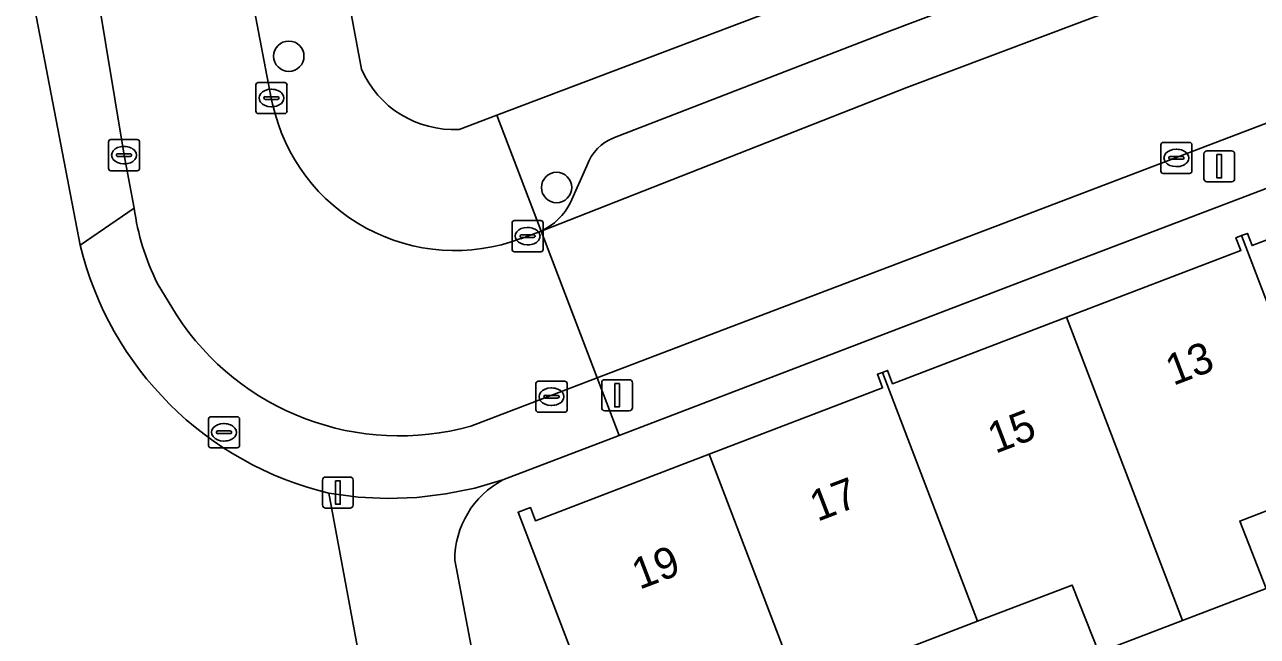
# Model space of a CAD drawing. Extents: x 159262 to 160143, y 383399 to 384319.
# Drawn here: x 159355.19 to 159394.93, y 383819.43 to 383839.14 of the extents above; entities that cross this region are included whole.
import ezdxf

# ---------------------------------------------------------------- set-up
doc = ezdxf.new("R2010")
doc.units = 0
for name, color, linetype in [('IMGEO_Boom', 7, 'Continuous'), ('IMGEO_Erf', 7, 'Continuous'), ('IMGEO_Groenvoorziening', 7, 'Continuous'), ('IMGEO_Kolk', 7, 'Continuous'), ('IMGEO_Lichtmast', 7, 'Continuous'), ('IMGEO_Pand', 7, 'Continuous'), ('IMGEO_Pand_nummerreeks', 7, 'Continuous'), ('IMGEO_Parkeervlak_open', 7, 'Continuous'), ('IMGEO_Rijbaan_lokaal_open', 7, 'Continuous'), ('IMGEO_Rioolput', 7, 'Continuous'), ('IMGEO_Voetpad_open', 7, 'Continuous')]:
    doc.layers.add(name, color=color, linetype=linetype)

msp = doc.modelspace()

# ---------------------------------------------------------------- linework, layer by layer
at = {"layer": 'IMGEO_Boom'}
for centre in [(159363.708, 383838.12), (159372.339, 383833.89)]:
    msp.add_circle(centre, 0.489, dxfattribs=at)
at = {"layer": 'IMGEO_Erf'}
for points in [[(159397.789, 383869.946), (159393.849, 383868.425), (159390.056, 383866.962), (159389.5, 383868.402), (159385.489, 383866.763), (159386.378, 383864.405), (159384.999, 383863.885), (159382.63, 383862.992), (159378.689, 383861.507), (159377.8, 383863.866), (159375.594, 383863.034), (159376.483, 383860.676), (159372.524, 383859.184), (159371.635, 383861.542), (159368.487, 383860.413), (159369.569, 383857.597), (159370.651, 383854.78), (159371.732, 383851.964), (159372.814, 383849.148), (159373.896, 383846.331), (159374.978, 383843.515), (159369.061, 383841.246), (159365.629, 383839.957), (159366.048, 383837.703)], [(159369.194, 383835.764), (159370.416, 383836.226), (159382.457, 383840.783), (159431.75, 383859.554)], [(159434.697, 383848.89), (159387.616, 383830.972), (159374.358, 383825.902), (159370.61, 383824.469)], [(159374.298, 383815.054), (159371.098, 383823.424), (159371.496, 383823.577), (159371.658, 383823.154), (159377.252, 383825.293), (159382.847, 383827.432), (159382.679, 383827.873), (159382.84, 383827.934), (159383.002, 383827.996), (159383.166, 383827.567), (159388.779, 383829.713), (159394.394, 383831.86), (159394.237, 383832.27), (159394.42, 383832.34), (159394.607, 383832.411), (159394.756, 383832.021), (159400.338, 383834.155)], [(159397.482, 383824.337), (159394.356, 383823.141), (159395.215, 383820.973), (159392.518, 383819.942), (159389.818, 383818.909), (159388.959, 383821.077), (159385.91, 383819.911), (159380.153, 383817.708)], [(159369.056, 383821.878), (159372.012, 383806.327), (159372.571, 383803.406), (159376.551, 383804.927), (159375.402, 383807.935), (159382.941, 383810.816), (159384.09, 383807.808), (159397.412, 383813.025), (159396.531, 383815.33), (159400.367, 383816.796), (159406.149, 383819.006), (159407.03, 383816.7), (159408.972, 383817.511), (159408.457, 383818.833), (159412.284, 383820.326), (159416.246, 383821.872), (159415.776, 383823.077)]]:
    msp.add_lwpolyline(points, dxfattribs=at)
for centre, radius, start, end in [((159369.017, 383838.998), 3.239, 203.5692, 273.1366), ((159371.982, 383821.884), 2.926, 117.9652, 180.1268)]:
    msp.add_arc(centre, radius, start, end, dxfattribs=at)
at = {"layer": 'IMGEO_Groenvoorziening'}
for points in [[(159354.9, 383842.891), (159350.307, 383841.994), (159347.636, 383855.565), (159344.735, 383870.683), (159342.623, 383870.295), (159354.405, 383809.755), (159367.99, 383812.463), (159367.685, 383814.072), (159369.306, 383814.377), (159368.687, 383817.552), (159366.931, 383817.307), (159366.196, 383817.565), (159364.998, 383824.037)], [(159356.981, 383832.035), (159354.9, 383842.891)]]:
    msp.add_lwpolyline(points, dxfattribs=at)
msp.add_arc((159367.542, 383834.604), 10.869, 193.672, 256.4639, dxfattribs=at)
at = {"layer": 'IMGEO_Kolk'}
for p, q in [((159362.648, 383836.348), (159362.648, 383837.2)), ((159362.723, 383837.274), (159363.575, 383837.274)), ((159363.136, 383837.054), (159363.161, 383837.054)), ((159363.649, 383837.2), (159363.649, 383836.348)), ((159362.907, 383836.768), (159362.907, 383836.78)), ((159363.345, 383836.731), (159362.947, 383836.731)), ((159362.95, 383836.817), (159363.348, 383836.817)), ((159363.391, 383836.78), (159363.391, 383836.768)), ((159363.575, 383836.274), (159362.723, 383836.274)), ((159363.159, 383836.494), (159363.134, 383836.494)), ((159357.971, 383835.432), (159358.823, 383835.432)), ((159357.896, 383834.506), (159357.896, 383835.358)), ((159358.384, 383835.212), (159358.409, 383835.212)), ((159358.897, 383835.358), (159358.897, 383834.506)), ((159391.816, 383834.416), (159391.816, 383835.268)), ((159391.891, 383835.342), (159392.743, 383835.342)), ((159392.304, 383835.122), (159392.329, 383835.122)), ((159392.817, 383835.268), (159392.817, 383834.416)), ((159358.155, 383834.926), (159358.155, 383834.938)), ((159358.593, 383834.889), (159358.195, 383834.889)), ((159358.198, 383834.975), (159358.596, 383834.975)), ((159358.407, 383834.652), (159358.382, 383834.652)), ((159358.639, 383834.938), (159358.639, 383834.926)), ((159392.075, 383834.836), (159392.075, 383834.848)), ((159392.513, 383834.799), (159392.115, 383834.799)), ((159392.118, 383834.885), (159392.516, 383834.885)), ((159392.559, 383834.848), (159392.559, 383834.836)), ((159358.823, 383834.432), (159357.971, 383834.432)), ((159392.743, 383834.342), (159391.891, 383834.342)), ((159392.327, 383834.562), (159392.302, 383834.562)), ((159370.902, 383831.896), (159370.902, 383832.748)), ((159370.977, 383832.822), (159371.829, 383832.822)), ((159371.903, 383832.748), (159371.903, 383831.896)), ((159371.161, 383832.316), (159371.161, 383832.328)), ((159371.599, 383832.279), (159371.201, 383832.279)), ((159371.204, 383832.365), (159371.602, 383832.365)), ((159371.39, 383832.602), (159371.415, 383832.602)), ((159371.645, 383832.328), (159371.645, 383832.316)), ((159371.829, 383831.822), (159370.977, 383831.822)), ((159371.413, 383832.042), (159371.388, 383832.042)), ((159371.674, 383826.724), (159371.674, 383827.576)), ((159371.749, 383827.65), (159372.601, 383827.65)), ((159372.675, 383827.576), (159372.675, 383826.724)), ((159371.933, 383827.144), (159371.933, 383827.156)), ((159372.371, 383827.107), (159371.973, 383827.107)), ((159371.976, 383827.193), (159372.374, 383827.193)), ((159372.162, 383827.43), (159372.187, 383827.43)), ((159372.417, 383827.156), (159372.417, 383827.144)), ((159372.601, 383826.65), (159371.749, 383826.65)), ((159372.185, 383826.87), (159372.16, 383826.87))]:
    msp.add_line(p, q, dxfattribs=at)
for points in [[(159362.648, 383836.348), (159362.648, 383837.2)], [(159362.723, 383837.274), (159363.575, 383837.274)], [(159363.649, 383837.2), (159363.649, 383836.348)], [(159363.575, 383836.274), (159362.723, 383836.274)], [(159357.971, 383835.432), (159358.823, 383835.432)], [(159357.896, 383834.506), (159357.896, 383835.358)], [(159358.897, 383835.358), (159358.897, 383834.506)], [(159391.816, 383834.416), (159391.816, 383835.268)], [(159391.891, 383835.342), (159392.743, 383835.342)], [(159392.817, 383835.268), (159392.817, 383834.416)], [(159358.823, 383834.432), (159357.971, 383834.432)], [(159392.743, 383834.342), (159391.891, 383834.342)], [(159370.902, 383831.896), (159370.902, 383832.748)], [(159370.977, 383832.822), (159371.829, 383832.822)], [(159371.903, 383832.748), (159371.903, 383831.896)], [(159371.829, 383831.822), (159370.977, 383831.822)], [(159371.674, 383826.724), (159371.674, 383827.576)], [(159371.749, 383827.65), (159372.601, 383827.65)], [(159372.675, 383827.576), (159372.675, 383826.724)], [(159372.601, 383826.65), (159371.749, 383826.65)]]:
    msp.add_lwpolyline(points, dxfattribs=at)
for centre, radius, start, end in [((159362.725, 383837.198), 0.0765, 91.552, 178.448), ((159362.725, 383837.198), 0.0765, 91.552, 178.448), ((159363.573, 383837.198), 0.0765, 1.552, 88.448), ((159363.573, 383837.198), 0.0765, 1.552, 88.448), ((159362.947, 383836.777), 0.0403, 85.8775, 175.7526), ((159362.944, 383836.767), 0.0366, 178.938, 274.7102), ((159363.348, 383836.774), 0.043, 264.8664, 352.4533), ((159363.352, 383836.779), 0.0386, 1.7309, 96.639), ((159362.725, 383836.35), 0.0765, 181.552, 268.448), ((159362.725, 383836.35), 0.0765, 181.552, 268.448), ((159363.573, 383836.35), 0.0765, 271.552, 358.448), ((159363.573, 383836.35), 0.0765, 271.552, 358.448), ((159357.973, 383835.356), 0.0765, 91.552, 178.448), ((159357.973, 383835.356), 0.0765, 91.552, 178.448), ((159358.821, 383835.356), 0.0765, 1.552, 88.448), ((159358.821, 383835.356), 0.0765, 1.552, 88.448), ((159391.893, 383835.266), 0.0765, 91.552, 178.448), ((159391.893, 383835.266), 0.0765, 91.552, 178.448), ((159392.741, 383835.266), 0.0765, 1.552, 88.448), ((159392.741, 383835.266), 0.0765, 1.552, 88.448), ((159358.195, 383834.935), 0.0403, 85.8775, 175.7526), ((159358.192, 383834.925), 0.0366, 178.938, 274.7102), ((159358.596, 383834.932), 0.043, 264.8664, 352.4533), ((159358.6, 383834.937), 0.0386, 1.7309, 96.639), ((159392.115, 383834.845), 0.0403, 85.8775, 175.7526), ((159392.112, 383834.835), 0.0366, 178.938, 274.7102), ((159392.516, 383834.842), 0.043, 264.8664, 352.4533), ((159392.52, 383834.847), 0.0386, 1.7309, 96.639), ((159357.973, 383834.508), 0.0765, 181.552, 268.448), ((159357.973, 383834.508), 0.0765, 181.552, 268.448), ((159358.821, 383834.508), 0.0765, 271.552, 358.448), ((159358.821, 383834.508), 0.0765, 271.552, 358.448), ((159391.893, 383834.418), 0.0765, 181.552, 268.448), ((159391.893, 383834.418), 0.0765, 181.552, 268.448), ((159392.741, 383834.418), 0.0765, 271.552, 358.448), ((159392.741, 383834.418), 0.0765, 271.552, 358.448), ((159370.979, 383832.746), 0.0765, 91.552, 178.448), ((159370.979, 383832.746), 0.0765, 91.552, 178.448), ((159371.827, 383832.746), 0.0765, 1.552, 88.448), ((159371.827, 383832.746), 0.0765, 1.552, 88.448), ((159371.201, 383832.325), 0.0403, 85.8775, 175.7526), ((159371.198, 383832.315), 0.0366, 178.938, 274.7102), ((159371.602, 383832.322), 0.043, 264.8664, 352.4533), ((159371.606, 383832.327), 0.0386, 1.7309, 96.639), ((159370.979, 383831.898), 0.0765, 181.552, 268.448), ((159370.979, 383831.898), 0.0765, 181.552, 268.448), ((159371.827, 383831.898), 0.0765, 271.552, 358.448), ((159371.827, 383831.898), 0.0765, 271.552, 358.448), ((159371.751, 383827.574), 0.0765, 91.552, 178.448), ((159371.751, 383827.574), 0.0765, 91.552, 178.448), ((159372.599, 383827.574), 0.0765, 1.552, 88.448), ((159372.599, 383827.574), 0.0765, 1.552, 88.448), ((159371.973, 383827.153), 0.0403, 85.8775, 175.7526), ((159371.97, 383827.143), 0.0366, 178.938, 274.7102), ((159372.374, 383827.15), 0.043, 264.8664, 352.4533), ((159372.378, 383827.155), 0.0386, 1.7309, 96.639), ((159371.751, 383826.726), 0.0765, 181.552, 268.448), ((159371.751, 383826.726), 0.0765, 181.552, 268.448), ((159372.599, 383826.726), 0.0765, 271.552, 358.448), ((159372.599, 383826.726), 0.0765, 271.552, 358.448)]:
    msp.add_arc(centre, radius, start, end, dxfattribs=at)
for centre, major_axis, ratio, start_param, end_param in [((159363.135, 383836.774), (-0.387, 0.002), 0.722429, 4.712389, 7.853982), ((159363.16, 383836.774), (-0.39, 0.002), 0.717154, 1.570796, 4.712389), ((159358.383, 383834.932), (-0.387, 0.002), 0.722429, 4.712389, 7.853982), ((159358.408, 383834.932), (-0.39, 0.002), 0.717154, 1.570796, 4.712389), ((159392.303, 383834.842), (-0.387, 0.002), 0.722429, 4.712389, 7.853982), ((159392.328, 383834.842), (-0.39, 0.002), 0.717154, 1.570796, 4.712389), ((159371.389, 383832.322), (-0.387, 0.002), 0.722429, 4.712389, 7.853982), ((159371.414, 383832.322), (-0.39, 0.002), 0.717154, 1.570796, 4.712389), ((159372.161, 383827.15), (-0.387, 0.002), 0.722429, 4.712389, 7.853982), ((159372.186, 383827.15), (-0.39, 0.002), 0.717154, 1.570796, 4.712389)]:
    msp.add_ellipse(centre, major_axis=major_axis, ratio=ratio, start_param=start_param, end_param=end_param, dxfattribs=at)
at = {"layer": 'IMGEO_Lichtmast'}
for p, q in [((159393.303, 383835.074), (159394.093, 383835.074)), ((159394.093, 383835.074), (159393.303, 383835.074)), ((159393.203, 383834.174), (159393.203, 383834.974)), ((159393.203, 383834.974), (159393.203, 383834.174)), ((159394.193, 383834.974), (159394.193, 383834.174)), ((159394.193, 383834.174), (159394.193, 383834.974)), ((159394.093, 383834.074), (159393.303, 383834.074)), ((159393.303, 383834.074), (159394.093, 383834.074)), ((159373.793, 383826.795), (159373.793, 383827.595)), ((159373.793, 383827.595), (159373.793, 383826.795)), ((159373.893, 383827.695), (159374.683, 383827.695)), ((159374.683, 383827.695), (159373.893, 383827.695)), ((159374.783, 383827.595), (159374.783, 383826.795)), ((159374.783, 383826.795), (159374.783, 383827.595)), ((159374.683, 383826.695), (159373.893, 383826.695)), ((159373.893, 383826.695), (159374.683, 383826.695)), ((159364.793, 383823.66), (159364.793, 383824.46)), ((159364.793, 383824.46), (159364.793, 383823.66)), ((159364.893, 383824.56), (159365.683, 383824.56)), ((159365.683, 383824.56), (159364.893, 383824.56)), ((159365.783, 383824.46), (159365.783, 383823.66)), ((159365.783, 383823.66), (159365.783, 383824.46)), ((159365.683, 383823.56), (159364.893, 383823.56)), ((159364.893, 383823.56), (159365.683, 383823.56))]:
    msp.add_line(p, q, dxfattribs=at)
for points in [[(159393.623, 383834.949), (159393.773, 383834.949), (159393.773, 383834.199), (159393.623, 383834.199), (159393.623, 383834.949)], [(159374.213, 383827.57), (159374.363, 383827.57), (159374.363, 383826.82), (159374.213, 383826.82), (159374.213, 383827.57)], [(159365.213, 383824.435), (159365.363, 383824.435), (159365.363, 383823.685), (159365.213, 383823.685), (159365.213, 383824.435)]]:
    msp.add_lwpolyline(points, dxfattribs=at)
for centre, start, end in [((159393.303, 383834.974), 90, 180), ((159393.303, 383834.974), 90, 180), ((159394.093, 383834.974), 0, 90), ((159394.093, 383834.974), 360, 90), ((159393.303, 383834.174), 180, 270), ((159393.303, 383834.174), 180, 270), ((159394.093, 383834.174), 270, 0), ((159394.093, 383834.174), 270, 0), ((159373.893, 383827.595), 90, 180), ((159373.893, 383827.595), 90, 180), ((159374.683, 383827.595), 0, 90), ((159374.683, 383827.595), 360, 90), ((159373.893, 383826.795), 180, 270), ((159373.893, 383826.795), 180, 270), ((159374.683, 383826.795), 270, 0), ((159374.683, 383826.795), 270, 0), ((159364.893, 383824.46), 90, 180), ((159364.893, 383824.46), 90, 180), ((159365.683, 383824.46), 0, 90), ((159365.683, 383824.46), 360, 90), ((159364.893, 383823.66), 180, 270), ((159364.893, 383823.66), 180, 270), ((159365.683, 383823.66), 270, 0), ((159365.683, 383823.66), 270, 0)]:
    msp.add_arc(centre, 0.1, start, end, dxfattribs=at)
at = {"layer": 'IMGEO_Pand'}
for points in [[(159397.482, 383824.337), (159403.251, 383826.543), (159400.338, 383834.155), (159394.756, 383832.021), (159394.607, 383832.411), (159394.42, 383832.34)], [(159397.482, 383824.337), (159394.42, 383832.34), (159394.237, 383832.27), (159394.394, 383831.86), (159388.779, 383829.713), (159392.518, 383819.942), (159395.215, 383820.973), (159394.356, 383823.141)], [(159392.518, 383819.942), (159388.779, 383829.713), (159383.166, 383827.567), (159383.002, 383827.996), (159382.84, 383827.934), (159385.91, 383819.911), (159388.959, 383821.077), (159389.818, 383818.909)], [(159382.84, 383827.934), (159382.679, 383827.873), (159382.847, 383827.432), (159377.252, 383825.293), (159380.153, 383817.708), (159385.91, 383819.911)], [(159377.252, 383825.293), (159371.658, 383823.154), (159371.496, 383823.577), (159371.098, 383823.424), (159374.298, 383815.054), (159374.978, 383813.275), (159380.773, 383815.492), (159379.954, 383817.632), (159380.153, 383817.708)]]:
    msp.add_lwpolyline(points, close=True, dxfattribs=at)
at = {"layer": 'IMGEO_Parkeervlak_open'}
for points in [[(159427.802, 383855.889), (159411.178, 383849.519), (159383.074, 383838.931), (159374.2, 383835.498)], [(159371.844, 383832.486), (159383.623, 383837.11), (159411.861, 383847.734), (159430.92, 383855.178)], [(159373.313, 383834.587), (159372.784, 383833.41)]]:
    msp.add_lwpolyline(points, dxfattribs=at)
for centre, radius, start, end in [((159374.719, 383834.105), 1.486, 110.4369, 161.0926), ((159370.982, 383834.303), 2.012, 295.3846, 333.6318)]:
    msp.add_arc(centre, radius, start, end, dxfattribs=at)
at = {"layer": 'IMGEO_Rijbaan_lokaal_open'}
for points in [[(159349.939, 383879.282), (159350.139, 383878.285), (159350.877, 383874.361), (159351.177, 383872.768), (159351.327, 383871.914), (159351.349, 383871.798), (159352.333, 383866.611), (159353.392, 383861.174), (159353.566, 383860.305), (159354.188, 383856.861), (159354.311, 383856.268), (159354.446, 383855.504), (159356.402, 383845.497), (159356.907, 383843.958), (159358.398, 383834.932), (159358.725, 383833.228)], [(159363.187, 383836.575), (159363.144, 383836.774), (159355.936, 383874.476)], [(159369.576, 383826.202), (159373.65, 383827.758), (159371.844, 383832.486), (159371.589, 383832.386), (159371.399, 383832.321), (159371.184, 383832.241)], [(159359.467, 383830.805), (159360.085, 383829.784)]]:
    msp.add_lwpolyline(points, dxfattribs=at)
msp.add_lwpolyline([(159432.041, 383850.161), (159432.689, 383850.402), (159433.465, 383850.712), (159431.695, 383855.47), (159431.498, 383855.404), (159431.28, 383855.319), (159430.92, 383855.178), (159411.861, 383847.734), (159383.623, 383837.11), (159371.844, 383832.486), (159373.65, 383827.758), (159377.676, 383829.295), (159387.324, 383832.951), (159404.16, 383839.368), (159413.728, 383842.98)], close=True, dxfattribs=at)
for centre, radius, start, end in [((159369.066, 383837.879), 6.022, 192.5024, 290.5864), ((159366.235, 383834.203), 7.572, 187.3942, 206.6583), ((159367.27, 383834.457), 8.571, 213.0399, 285.606)]:
    msp.add_arc(centre, radius, start, end, dxfattribs=at)
at = {"layer": 'IMGEO_Rioolput'}
for p, q in [((159361.118, 383825.575), (159361.118, 383826.427)), ((159361.193, 383826.501), (159362.045, 383826.501)), ((159361.606, 383826.281), (159361.631, 383826.281)), ((159362.119, 383826.427), (159362.119, 383825.575)), ((159361.377, 383825.995), (159361.377, 383826.007)), ((159361.815, 383825.958), (159361.417, 383825.958)), ((159361.42, 383826.044), (159361.818, 383826.044)), ((159361.861, 383826.007), (159361.861, 383825.995)), ((159362.045, 383825.501), (159361.193, 383825.501)), ((159361.629, 383825.721), (159361.604, 383825.721))]:
    msp.add_line(p, q, dxfattribs=at)
for points in [[(159361.118, 383825.575), (159361.118, 383826.427)], [(159361.193, 383826.501), (159362.045, 383826.501)], [(159362.119, 383826.427), (159362.119, 383825.575)], [(159362.045, 383825.501), (159361.193, 383825.501)]]:
    msp.add_lwpolyline(points, dxfattribs=at)
for centre, radius, start, end in [((159361.195, 383826.425), 0.0765, 91.552, 178.448), ((159361.195, 383826.425), 0.0765, 91.552, 178.448), ((159362.043, 383826.425), 0.0765, 1.552, 88.448), ((159362.043, 383826.425), 0.0765, 1.552, 88.448), ((159361.417, 383826.004), 0.0403, 85.8775, 175.7526), ((159361.414, 383825.994), 0.0366, 178.938, 274.7102), ((159361.818, 383826.001), 0.043, 264.8664, 352.4533), ((159361.822, 383826.006), 0.0386, 1.7309, 96.639), ((159361.195, 383825.577), 0.0765, 181.552, 268.448), ((159361.195, 383825.577), 0.0765, 181.552, 268.448), ((159362.043, 383825.577), 0.0765, 271.552, 358.448), ((159362.043, 383825.577), 0.0765, 271.552, 358.448)]:
    msp.add_arc(centre, radius, start, end, dxfattribs=at)
for centre, major_axis, ratio, start_param, end_param in [((159361.605, 383826.001), (-0.387, 0.002), 0.722429, 4.712389, 7.853982), ((159361.63, 383826.001), (-0.39, 0.002), 0.717154, 1.570796, 4.712389)]:
    msp.add_ellipse(centre, major_axis=major_axis, ratio=ratio, start_param=start_param, end_param=end_param, dxfattribs=at)
at = {"layer": 'IMGEO_Voetpad_open'}
for points in [[(159355.685, 383875.681), (159355.936, 383874.476), (159363.144, 383836.774), (159363.187, 383836.575)], [(159431.75, 383859.554), (159382.457, 383840.783), (159370.416, 383836.226), (159371.844, 383832.486)], [(159366.048, 383837.703), (159365.629, 383839.957), (159362.134, 383857.975)], [(159374.2, 383835.498), (159383.074, 383838.931), (159411.178, 383849.519), (159427.802, 383855.889)], [(159434.05, 383850.932), (159433.465, 383850.712), (159432.689, 383850.402), (159432.041, 383850.161), (159413.728, 383842.98), (159404.16, 383839.368), (159387.324, 383832.951), (159377.676, 383829.295), (159373.65, 383827.758), (159374.358, 383825.902), (159387.616, 383830.972)], [(159387.616, 383830.972), (159434.697, 383848.89)], [(159356.372, 383843.192), (159354.9, 383842.891), (159356.981, 383832.035), (159358.725, 383833.228), (159358.398, 383834.932), (159356.907, 383843.958)], [(159371.184, 383832.241), (159371.399, 383832.321), (159371.589, 383832.386), (159371.844, 383832.486), (159370.416, 383836.226), (159369.194, 383835.764)], [(159372.784, 383833.41), (159373.313, 383834.587)], [(159358.725, 383833.228), (159356.981, 383832.035)], [(159360.085, 383829.784), (159359.467, 383830.805)], [(159364.998, 383824.037), (159365.938, 383823.916), (159366.884, 383823.872), (159367.831, 383823.906), (159368.771, 383824.018), (159369.7, 383824.206), (159370.61, 383824.469), (159374.358, 383825.902), (159373.65, 383827.758), (159369.576, 383826.202)], [(159370.61, 383824.469), (159369.7, 383824.206), (159368.771, 383824.018), (159367.831, 383823.906), (159366.884, 383823.872), (159365.938, 383823.916), (159364.998, 383824.037), (159366.196, 383817.565), (159366.931, 383817.307), (159368.687, 383817.552), (159369.306, 383814.377), (159367.685, 383814.072), (159367.99, 383812.463), (159369.337, 383805.354), (159372.012, 383806.327), (159369.056, 383821.878)]]:
    msp.add_lwpolyline(points, dxfattribs=at)
for centre, radius, start, end in [((159369.017, 383838.998), 3.239, 203.5692, 273.1366), ((159369.066, 383837.879), 6.022, 192.5024, 290.5864), ((159374.719, 383834.105), 1.486, 110.4369, 161.0926), ((159370.982, 383834.303), 2.012, 295.3846, 333.6318), ((159366.235, 383834.203), 7.572, 187.3942, 206.6583), ((159367.542, 383834.604), 10.869, 193.672, 256.4639), ((159367.27, 383834.457), 8.571, 213.0399, 285.606), ((159371.982, 383821.884), 2.926, 117.9652, 180.1268)]:
    msp.add_arc(centre, radius, start, end, dxfattribs=at)

# ---------------------------------------------------------------- texts
at = {"layer": 'IMGEO_Pand_nummerreeks'}
for s, rotation, p in [('13', 20.9052, (159392.215, 383827.495)), ('15', 20.9052, (159386.48, 383825.305)), ('17', 20.9052, (159380.745, 383823.114)), ('19', 20.9072, (159375.009, 383820.923))]:
    msp.add_text(s, height=1, rotation=rotation, dxfattribs=at).set_placement(p)

doc.saveas('drawing.dxf')
